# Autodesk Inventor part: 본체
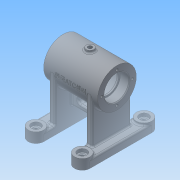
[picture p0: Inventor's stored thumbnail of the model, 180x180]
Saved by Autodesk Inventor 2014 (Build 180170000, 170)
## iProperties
Created: 2015-11
Part Number: 본체
Material: 알루미늄 6061
Document SubType Name: Modeling
Designer: net
Density: 2.71 g/cm^3
Appearance: 알루미늄 - 평지
Mass: 359.021 g
Surface Area: 459.454 cm^2
Volume: 132.48 cm^3
Author: net
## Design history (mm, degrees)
sketch "스케치1"
  geometry: C1 r 25 at (0, 0); 1 further point
  constraints: 1 centre point, 1 coincident
  dimensions: "d0" = 50 diameter of C1
extrude "돌출1" new body sketch "스케치1" distance "d1" = 70; taper "d2" = 0 deg
sketch "스케치2"
  geometry: C1 r 25 at (0, 0) reference; C2 r 16 at (0, 0)
  constraints: 1 centre point, 1 coincident
  dimensions: "d3" = 32 diameter of C2
extrude "돌출2" cut sketch "스케치2" distance "d4" = 12; taper "d5" = 0 deg
sketch "스케치3"
  geometry: C1 r 16 at (0, 0) reference; C2 r 14 at (0, 0)
  constraints: 1 centre point, 1 coincident
  dimensions: "d6" = 28 diameter of C2
extrude "돌출3" cut sketch "스케치3" distance "d7" = 2; taper "d8" = 0 deg
sketch "스케치4"
  geometry: C1 r 14 at (0, 0) reference; C2 r 21 at (0, 0)
  constraints: 1 centre point, 1 coincident
  dimensions: "d9" = 42 diameter of C2
extrude "돌출4" cut sketch "스케치4" distance "d10" = 42; taper "d11" = 0 deg
sketch "스케치5"
  geometry: C1 r 21 at (0, 0) reference; C2 r 14 at (0, 0)
  constraints: 1 centre point, 1 coincident
  dimensions: "d12" = 28 diameter of C2
extrude "돌출5" cut sketch "스케치5" distance "d13" = 2; taper "d14" = 0 deg
sketch "스케치6"
  geometry: C1 r 25 at (0, 0) reference; C2 r 16 at (0, 0)
  constraints: 1 centre point, 1 coincident
  dimensions: "d15" = 32 diameter of C2
extrude "돌출6" cut sketch "스케치6" distance "d16" = 12; taper "d17" = 0 deg
fillet "모깎기1" dims "d18" = 0.3
chamfer "모따기1" distance "d19" = 1; stored, may be unused: second distance "d20" = 2, angle "d21" = 45 deg
node "작업 평면2"
  node "작업 평면1"
sketch "스케치7"
  geometry: L1 (-25, 0)-(25, 0) reference; C1 r 5 at (0, 35); 1 further point
  constraints: 1 centre point
  dimensions: "d23" = 10 diameter of C1; "d24" = 35 distance from line of L1 C1.centre
extrude "돌출7" join sketch "스케치7" stored distance "d25" = 12; taper "d26" = 0 deg
fillet "모깎기2" dims "d27" = 2
sketch "스케치8"
  geometry: C1 r 5 at (0, 0) reference; 1 further point
hole "구멍1" sketch "스케치8" at (0, 0) diameter "d28" = 5.188; stored, may be unused: countersink angle "d32" = 90 deg, drill point angle "d34" = 118 deg; dims "d29" = 8, "d30" = 4, "d31" = 2, "d33" = 8
fillet "모깎기3" dims "d35" = 3
sketch "스케치9"
  geometry: C1 r 17 at (0, 0) reference; A1 r 20 centre (0, 0) between (0, 20) and (20, 0); 2 further points
  constraints: 4 point on circle, 1 centre point, 1 coincident
  dimensions: "d36" = 40 diameter of A1
hole "구멍2" sketch "스케치9" at (0, 20), (20, 0), (0, -20), (-20, 0) diameter "d37" = 3.242; stored, may be unused: countersink angle "d41" = 90 deg, drill point angle "d43" = 118 deg; dims "d38" = 8, "d39" = 4, "d40" = 2, "d42" = 10
sketch "스케치10"
  geometry: C1 r 17 at (0, 0) reference; A1 r 20 centre (0, 0) between (0, 20) and (20, 0); 2 further points
  constraints: 4 point on circle, 1 centre point, 1 coincident
  dimensions: "d44" = 40 diameter of A1
hole "구멍3" sketch "스케치10" at (0, 20), (20, 0), (0, -20), (-20, 0) diameter "d45" = 3.242; stored, may be unused: countersink angle "d49" = 90 deg, drill point angle "d51" = 118 deg; dims "d46" = 8, "d47" = 4, "d48" = 2, "d50" = 10
node "작업 평면4"
sketch "스케치11"
  geometry: L1 (0, 0)-(0, -25); L2 (0, 0)-(12.5, -21.651); L3 (12.5, -21.651)-(14, -24.249); L4 (14, -24.249)-(19.196, -21.249); L5 (19.196, -21.249)-(17.331, -18.018); A1 r 25 centre (0, 0) between (0, -25) and (12.5, -21.651) reference; 1 further point
  constraints: 10 end point, 3 point on circle, 2 perpendicular, 1 collinear, 1 vertical
  dimensions: "d53" = 30 deg angle of L2 L1; "d54" = 12 diameter of L4.end L3; "d55" = 28 distance from line of L4 point (0, 0)
revolve "회전1" sketch "스케치11" stored, may be unused: angle "d56" = 90 deg
sketch "스케치12"
  geometry: C1 r 6 at (0, 0) reference; 1 further point
hole "구멍4" sketch "스케치12" at (0, 0) diameter "d57" = 5.188; stored, may be unused: countersink angle "d61" = 90 deg, drill point angle "d63" = 118 deg; dims "d58" = 8, "d59" = 4, "d60" = 2, "d62" = 10
node "작업 평면5"
node "작업 평면6"
node "작업 평면7"
node "작업 평면8"
sketch "스케치15"
  geometry: L1 (-25, 0)-(-25, 70) reference; L2 (-25, 35)-(-17.013, 35); L3 (25, 70)-(-25, 70) reference; L4 (0, 70)-(0, 56.054); C1 r 10 at (40, 65); C2 r 10 at (-40, 65); 1 further point
  constraints: 4 end point, 2 centre point, 2 midpoint, 2 perpendicular, 1 symmetric about line, 1 other
  dimensions: "d81" = 20 diameter of C1; "d93" = 80 distance of C1.centre C2.centre; "d94" = 30 vertical distance of L2.end C2.centre
extrude "돌출10" join sketch "스케치15" distance "d89" = 13; taper "d90" = 0 deg
sketch "스케치16"
  geometry: L1 (-80, 10)-(0, 10); L2 (-80, -10)-(0, -10); A1 r 10 centre (0, 0) between (0, 10) and (0, -10) reference; A2 r 10 centre (-80, 0) between (-80, 10) and (-80, -10) reference; 1 further point
  constraints: 4 end point, 4 point on circle, 4 tangent
extrude "돌출11" join sketch "스케치16" distance "d91" = 10; taper "d92" = 0 deg
node "작업 평면9"
node "작업 평면12"
node "작업 평면14"
  node "작업 평면13"
sketch "스케치18"
  geometry: L1 (0, 10)-(80, 10) reference; L2 (15, 68)-(15, 10); L3 (65, 68)-(65, 10); A1 r 25 centre (40, 68) between (15, 68) and (65, 68) reference; 1 further point
  constraints: 4 end point, 2 perpendicular, 2 point on circle, 2 point on line, 2 tangent
extrude "돌출13" join sketch "스케치18" distance "d102" = 8; taper "d103" = 0 deg
node "작업 평면15"
fillet "모깎기7" dims "d105" = 2
sketch "스케치19"
  geometry: L1 (-25, 0)-(-25, 70) reference; L2 (-14.142, 55)-(-56, 55) reference; L3 (-56, 15)-(-9.798, 15) reference; L4 (-45, 55)-(-45, 15); L5 (-45, 55)-(-25, 55); L6 (-25, 55)-(-25, 15); L7 (-25, 15)-(-45, 15); L8 (-25, 55)-(-22.901, 55); L9 (-22.901, 15)-(-22.901, 55); L10 (-22.901, 15)-(-25, 15); 2 further points
  constraints: 14 end point, 8 point on line, 2 perpendicular, 1 collinear, 1 parallel
  dimensions: "d108" = 20 distance between parallel lines of L1 L4
extrude "돌출14" join sketch "스케치19" stored distance "d109" = 8; taper "d110" = 0 deg
fillet "모깎기10" dims "d111" = 2
fillet "모깎기11" dims "d112" = 2
fillet "모깎기12" dims "d113" = 2
fillet "모깎기13" dims "d114" = 2
fillet "모깎기14" dims "d115" = 2
sketch "스케치20"
  geometry: L1 (53, -43)-(17, -43) reference; L2 (17, -43)-(17, -26.325) reference; L3 (27, -31.5)-(43, -31.5); L4 (27, -38.5)-(43, -38.5); L5 (-5, -68)-(15, -68) reference; L6 (35, -43)-(35, -40.187); A1 r 3.5 centre (27, -35) between (27, -31.5) and (27, -38.5); A2 r 3.5 centre (43, -35) between (43, -31.5) and (43, -38.5); 1 further point
  constraints: 6 end point, 4 point on circle, 3 tangent, 2 centre point, 2 perpendicular, 1 midpoint, 1 parallel
  dimensions: "d116" = 7 diameter of A1; "d117" = 7 diameter of A2; "d118" = 33 distance from line of L5 A1.centre; "d121" = 11.5 dimension on A1 L6; "d122" = 11.5 dimension on A2 L6
extrude "돌출15" cut sketch "스케치20" distance "d123" = 8; taper "d124" = 0 deg
fillet "모깎기15" dims "d125" = 2
fillet "모깎기16" dims "d126" = 2
fillet "모깎기17" dims "d127" = 2
sketch "스케치21"
  geometry: C1 r 10 at (0, 0) reference; C2 r 6 at (0, 0); 1 further point
  constraints: 1 centre point, 1 coincident
  dimensions: "d128" = 12 diameter of C2
extrude "돌출16" cut sketch "스케치21" distance "d129" = 4; taper "d130" = 0 deg
fillet "모깎기18" dims "d131" = 0.3
sketch "스케치22"
  geometry: C1 r 3 at (0, -10); A1 r 10 centre (0, -10) between (0, 0) and (0, -20) reference; 1 further point
  constraints: 1 centre point, 1 coincident
  dimensions: "d132" = 6 diameter of C1
extrude "돌출17" cut sketch "스케치22" stored distance "d133" = 4; taper "d134" = 0 deg
chamfer "모따기2" distance "d135" = 1; stored, may be unused: second distance "d136" = 2, angle "d137" = 45 deg
node "작업 평면16"
node "작업 평면17"
sketch "스케치23"
  geometry: L1 (-18.817, 29.707)-(-18.817, 40.293); L2 (-18.817, 40.293)-(18.817, 40.293); L3 (18.817, 40.293)-(18.817, 29.707); L4 (18.817, 29.707)-(-18.817, 29.707); L5 (0, 29.707)-(0, 40.293); L6 (-18.817, 35)-(18.817, 35); L7 (-28, 30)-(-28, 40) reference; 2 further points
  constraints: 5 midpoint, 4 end point, 2 other
  dimensions: "d139" = 0 distance from line of point (-28, 35) L6; "d140" = 0 distance from line of point (0, 0) L5
feature "엠보싱1" sketch "스케치23" dims "d141" = 0.5, "d142" = 0
node "솔리드1"
mirror "대칭2"
mirror "대칭3"
mirror "대칭4"
mirror "대칭5"
mirror "대칭6"
other parameters: "d22" = 3, "d52" = 35, "d64" = 35, "d65" = -68, "d79" = 35, "d80" = -68, "d95" = 35, "d104" = 35, "d138" = 35
